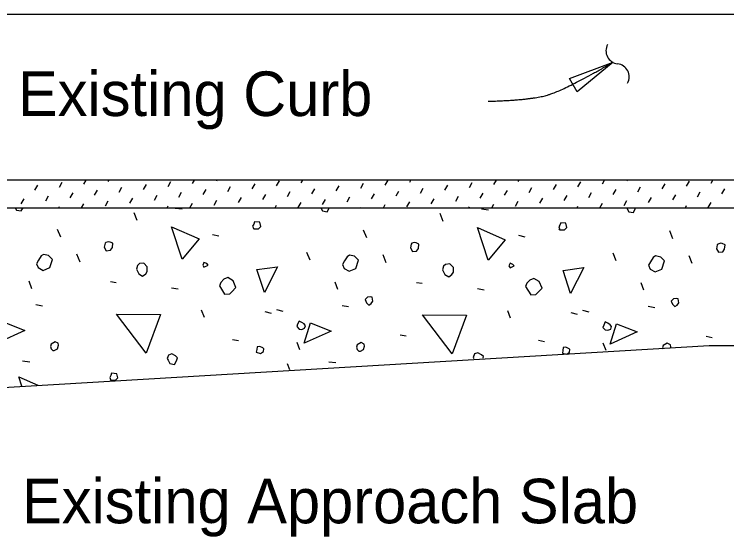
# Model space of a CAD drawing. Extents: x 21587 to 21656.3, y 56117.4 to 56157.3.
# Drawn here: x 21596.035 to 21599.259, y 56132.438 to 56134.801 of the extents above; entities that cross this region are included whole.
import ezdxf

# ---------------------------------------------------------------- set-up
doc = ezdxf.new("R2010")
doc.units = 0
for name, color, linetype in [('AdhocPoint_dp', 7, 'Continuous'), ('PlotBorder_dp', 7, 'Continuous'), ('SheetBorder_dp', 7, 'Continuous'), ('TextMisc', 7, 'Continuous')]:
    doc.layers.add(name, color=color, linetype=linetype)

msp = doc.modelspace()

# ---------------------------------------------------------------- linework, layer by layer
at = {"layer": 'AdhocPoint_dp'}
for p, q in [((21593.9596, 56134.8009), (21601.9067, 56134.8009)), ((21604.323, 56134.0511), (21593.9596, 56134.0511)), ((21593.9596, 56133.926), (21604.323, 56133.926)), ((21599.1795, 56133.301), (21594.9595, 56133.051)), ((21604.323, 56133.301), (21599.1795, 56133.301))]:
    msp.add_line(p, q, dxfattribs=at)
at = {"layer": 'PlotBorder_dp'}
msp.add_lwpolyline([(21598.7452, 56134.5845), (21598.5825, 56134.4497), (21598.5472, 56134.5108)], close=True, dxfattribs=at)
for centre, start, end in [((21598.7718, 56134.636), 151.5267, 263.2539), ((21598.7578, 56134.5176), 331.5267, 83.2539)]:
    msp.add_arc(centre, 0.0596, start, end, dxfattribs=at)
msp.add_open_spline([(21598.18, 56134.4075), (21598.3615, 56134.4123), (21598.5206, 56134.4547), (21598.7452, 56134.5845)], degree=2, dxfattribs=at)
at = {"layer": 'TextMisc'}
for p, q in [((21596.1289, 56134.0059), (21596.1418, 56134.0283)), ((21596.2395, 56134.0189), (21596.2525, 56134.0413)), ((21596.3501, 56134.0319), (21596.3613, 56134.0511)), ((21596.4608, 56134.0448), (21596.4644, 56134.0511)), ((21596.6202, 56134.009), (21596.6332, 56134.0314)), ((21596.7309, 56134.0219), (21596.7438, 56134.0443)), ((21596.8415, 56134.0349), (21596.8509, 56134.0511)), ((21596.9521, 56134.0479), (21596.954, 56134.0511)), ((21597.1116, 56134.012), (21597.1246, 56134.0344)), ((21597.2222, 56134.0249), (21597.2352, 56134.0473)), ((21597.3329, 56134.0379), (21597.3405, 56134.0511)), ((21597.4435, 56134.0509), (21597.4436, 56134.0511)), ((21597.4923, 56134.002), (21597.5053, 56134.0244)), ((21597.603, 56134.015), (21597.6159, 56134.0374)), ((21597.7136, 56134.028), (21597.7266, 56134.0504)), ((21597.8242, 56134.0409), (21597.8301, 56134.0511)), ((21597.9837, 56134.0051), (21597.9967, 56134.0275)), ((21598.0943, 56134.018), (21598.1073, 56134.0404)), ((21598.205, 56134.031), (21598.2166, 56134.0511)), ((21598.3156, 56134.044), (21598.3197, 56134.0511)), ((21598.4751, 56134.0081), (21598.488, 56134.0305)), ((21598.5857, 56134.021), (21598.5987, 56134.0434)), ((21598.6963, 56134.034), (21598.7062, 56134.0511)), ((21598.807, 56134.047), (21598.8094, 56134.0511)), ((21598.9664, 56134.0111), (21598.9794, 56134.0335)), ((21599.0771, 56134.0241), (21599.09, 56134.0465)), ((21599.1877, 56134.037), (21599.1958, 56134.0511)), ((21596.2883, 56133.9701), (21596.3013, 56133.9925)), ((21596.399, 56133.983), (21596.4119, 56134.0054)), ((21596.5096, 56133.996), (21596.5226, 56134.0184)), ((21596.7797, 56133.9731), (21596.7927, 56133.9955)), ((21596.8903, 56133.9861), (21596.9033, 56134.0084)), ((21597.001, 56133.999), (21597.0139, 56134.0214)), ((21597.2711, 56133.9761), (21597.284, 56133.9985)), ((21597.3817, 56133.9891), (21597.3947, 56134.0115)), ((21597.7624, 56133.9791), (21597.7754, 56134.0015)), ((21597.8731, 56133.9921), (21597.886, 56134.0145)), ((21598.2538, 56133.9822), (21598.2668, 56134.0045)), ((21598.3644, 56133.9951), (21598.3774, 56134.0175)), ((21598.6345, 56133.9722), (21598.6475, 56133.9946)), ((21598.7452, 56133.9852), (21598.7581, 56134.0076)), ((21598.8558, 56133.9981), (21598.8688, 56134.0205)), ((21599.1259, 56133.9752), (21599.1389, 56133.9976)), ((21599.2365, 56133.9882), (21599.2495, 56134.0106)), ((21596.0671, 56133.9441), (21596.08, 56133.9665)), ((21596.1777, 56133.9571), (21596.1907, 56133.9795)), ((21596.5584, 56133.9472), (21596.5714, 56133.9696)), ((21596.6691, 56133.9601), (21596.682, 56133.9825)), ((21597.0498, 56133.9502), (21597.0628, 56133.9726)), ((21597.1604, 56133.9631), (21597.1734, 56133.9855)), ((21597.4305, 56133.9402), (21597.4435, 56133.9626)), ((21597.5412, 56133.9532), (21597.5541, 56133.9756)), ((21597.6518, 56133.9662), (21597.6648, 56133.9886)), ((21597.9219, 56133.9433), (21597.9349, 56133.9657)), ((21598.0325, 56133.9562), (21598.0455, 56133.9786)), ((21598.1432, 56133.9692), (21598.1561, 56133.9916)), ((21598.4133, 56133.9463), (21598.4262, 56133.9687)), ((21598.5239, 56133.9592), (21598.5369, 56133.9816)), ((21598.9046, 56133.9493), (21598.9176, 56133.9717)), ((21599.0153, 56133.9623), (21599.0282, 56133.9847)), ((21596.2368, 56133.926), (21596.2395, 56133.9307)), ((21596.34, 56133.926), (21596.3501, 56133.9436)), ((21596.4478, 56133.9342), (21596.4608, 56133.9566)), ((21596.7264, 56133.926), (21596.7309, 56133.9337)), ((21596.8296, 56133.926), (21596.8415, 56133.9466)), ((21596.9392, 56133.9372), (21596.9521, 56133.9596)), ((21597.2161, 56133.926), (21597.2222, 56133.9367)), ((21597.3199, 56133.9273), (21597.3329, 56133.9497)), ((21597.7057, 56133.926), (21597.7136, 56133.9397)), ((21597.8113, 56133.9303), (21597.8242, 56133.9527)), ((21598.0922, 56133.926), (21598.0943, 56133.9298)), ((21598.1953, 56133.926), (21598.205, 56133.9427)), ((21598.3026, 56133.9333), (21598.3156, 56133.9557)), ((21598.5818, 56133.926), (21598.5857, 56133.9328)), ((21598.6849, 56133.926), (21598.6963, 56133.9458)), ((21598.794, 56133.9363), (21598.807, 56133.9587)), ((21599.0714, 56133.926), (21599.0771, 56133.9358)), ((21599.1747, 56133.9264), (21599.1877, 56133.9488)), ((21596.5913, 56133.8676), (21596.5771, 56133.903)), ((21596.7639, 56133.9236), (21596.7957, 56133.9201)), ((21597.6025, 56133.926), (21597.603, 56133.9268)), ((21597.9759, 56133.8641), (21597.9618, 56133.8995)), ((21598.1485, 56133.9201), (21598.1804, 56133.9165)), ((21596.2454, 56133.7928), (21596.2313, 56133.8281)), ((21596.9318, 56133.8051), (21596.9601, 56133.7981)), ((21597.6301, 56133.7892), (21597.6159, 56133.8246)), ((21598.3165, 56133.8016), (21598.3448, 56133.7945)), ((21599.0148, 56133.7857), (21599.0006, 56133.8211)), ((21596.3332, 56133.6803), (21596.319, 56133.7156)), ((21597.3737, 56133.6885), (21597.3596, 56133.7238)), ((21597.7178, 56133.6767), (21597.7037, 56133.7121)), ((21598.7584, 56133.6849), (21598.7443, 56133.7203)), ((21599.1025, 56133.6732), (21599.0884, 56133.7085)), ((21596.1146, 56133.5594), (21596.1022, 56133.593)), ((21596.471, 56133.5919), (21596.4958, 56133.5883)), ((21597.4993, 56133.5559), (21597.4869, 56133.5895)), ((21597.8557, 56133.5883), (21597.8805, 56133.5848)), ((21598.8839, 56133.5524), (21598.8716, 56133.5859)), ((21596.7468, 56133.5636), (21596.7769, 56133.5583)), ((21598.1315, 56133.5601), (21598.1615, 56133.5547)), ((21596.1334, 56133.4876), (21596.1635, 56133.4823)), ((21597.5181, 56133.484), (21597.5481, 56133.4787)), ((21598.9028, 56133.4805), (21598.9328, 56133.4752)), ((21596.8953, 56133.4292), (21596.8829, 56133.4628)), ((21597.1693, 56133.4558), (21597.1976, 56133.4487)), ((21597.2217, 56133.4657), (21597.25, 56133.4587)), ((21598.28, 56133.4257), (21598.2676, 56133.4593)), ((21598.554, 56133.4522), (21598.5823, 56133.4451)), ((21598.6064, 56133.4622), (21598.6347, 56133.4551)), ((21597.7815, 56133.3515), (21597.808, 56133.3462)), ((21597.0226, 56133.3302), (21597.0491, 56133.3249)), ((21597.3278, 56133.2831), (21597.3154, 56133.3167)), ((21598.4073, 56133.3267), (21598.4338, 56133.3214)), ((21599.1657, 56133.3444), (21599.1922, 56133.3391)), ((21598.7125, 56133.2796), (21598.7001, 56133.3132)), ((21596.0733, 56133.233), (21596.1051, 56133.2295)), ((21597.2818, 56133.1928), (21597.2712, 56133.2194)), ((21597.458, 56133.2295), (21597.4898, 56133.2259))]:
    msp.add_line(p, q, dxfattribs=at)
for points in [[(21596.0394, 56133.926), (21596.0456, 56133.9147), (21596.0669, 56133.9112), (21596.0751, 56133.926)], [(21597.4221, 56133.926), (21597.4303, 56133.9112), (21597.4515, 56133.9077), (21597.4604, 56133.9236), (21597.461, 56133.926)], [(21598.8049, 56133.926), (21598.8062, 56133.9236)], [(21598.8062, 56133.9236), (21598.815, 56133.9077), (21598.8362, 56133.9041), (21598.845, 56133.9201), (21598.8465, 56133.926)], [(21596.7945, 56133.6926), (21596.7468, 56133.8394), (21596.8723, 56133.7846), (21596.7945, 56133.6926)], [(21597.1192, 56133.8299), (21597.1404, 56133.8299), (21597.151, 56133.8405), (21597.1457, 56133.8599), (21597.1227, 56133.8617), (21597.1192, 56133.8511), (21597.1139, 56133.8423), (21597.1192, 56133.8299), (21597.1157, 56133.8334)], [(21598.1792, 56133.6891), (21598.1315, 56133.8358), (21598.257, 56133.781), (21598.1792, 56133.6891)], [(21598.5039, 56133.8264), (21598.5251, 56133.8264), (21598.5357, 56133.837), (21598.5304, 56133.8564), (21598.5074, 56133.8582), (21598.5039, 56133.8476), (21598.4986, 56133.8387), (21598.5039, 56133.8264), (21598.5003, 56133.8299)], [(21596.4428, 56133.7474), (21596.4516, 56133.7315), (21596.471, 56133.7333), (21596.4799, 56133.7457), (21596.4817, 56133.7651), (21596.4693, 56133.7704), (21596.4604, 56133.7722), (21596.4498, 56133.7686), (21596.4463, 56133.7651), (21596.4428, 56133.7474)], [(21597.8274, 56133.7439), (21597.8363, 56133.728), (21597.8557, 56133.7298), (21597.8646, 56133.7421), (21597.8663, 56133.7616), (21597.854, 56133.7669), (21597.8451, 56133.7686), (21597.8345, 56133.7651), (21597.831, 56133.7616), (21597.8274, 56133.7439)], [(21599.2121, 56133.7404), (21599.221, 56133.7245), (21599.2404, 56133.7262), (21599.2492, 56133.7386), (21599.251, 56133.758), (21599.2386, 56133.7633), (21599.2298, 56133.7651), (21599.2192, 56133.7616), (21599.2156, 56133.758), (21599.2121, 56133.7404)], [(21596.1429, 56133.6549), (21596.1658, 56133.6425), (21596.1959, 56133.6549), (21596.2083, 56133.692), (21596.1906, 56133.7097), (21596.1676, 56133.715), (21596.157, 56133.7079), (21596.1446, 56133.6885), (21596.1358, 56133.6726), (21596.1429, 56133.6549)], [(21597.5275, 56133.6514), (21597.5505, 56133.639), (21597.5806, 56133.6514), (21597.593, 56133.6885), (21597.5753, 56133.7062), (21597.5523, 56133.7115), (21597.5417, 56133.7044), (21597.5293, 56133.6849), (21597.5205, 56133.669), (21597.5275, 56133.6514)], [(21598.9122, 56133.6478), (21598.9352, 56133.6354), (21598.9653, 56133.6478), (21598.9776, 56133.6849), (21598.9599, 56133.7026), (21598.937, 56133.7079), (21598.9264, 56133.7008), (21598.914, 56133.6814), (21598.9051, 56133.6655), (21598.9122, 56133.6478)], [(21596.5877, 56133.6484), (21596.5983, 56133.6272), (21596.616, 56133.6166), (21596.6301, 56133.6272), (21596.6372, 56133.6378), (21596.6372, 56133.659), (21596.6213, 56133.675), (21596.6019, 56133.6732), (21596.593, 56133.6644), (21596.5877, 56133.6484)], [(21596.8935, 56133.6573), (21596.913, 56133.6661), (21596.9059, 56133.6732), (21596.8935, 56133.6785), (21596.8882, 56133.6661), (21596.8935, 56133.6573)], [(21597.9724, 56133.6449), (21597.983, 56133.6237), (21598.0007, 56133.6131), (21598.0148, 56133.6237), (21598.0219, 56133.6343), (21598.0219, 56133.6555), (21598.006, 56133.6714), (21597.9865, 56133.6697), (21597.9777, 56133.6608), (21597.9724, 56133.6449)], [(21598.2782, 56133.6537), (21598.2977, 56133.6626), (21598.2906, 56133.6697), (21598.2782, 56133.675), (21598.2729, 56133.6626), (21598.2782, 56133.6537)], [(21597.1669, 56133.5417), (21597.1333, 56133.646), (21597.227, 56133.6584), (21597.1669, 56133.5417)], [(21598.5516, 56133.5382), (21598.518, 56133.6425), (21598.6117, 56133.6549), (21598.5516, 56133.5382)], [(21596.9643, 56133.5724), (21596.9872, 56133.5353), (21597.0102, 56133.5371), (21597.0191, 56133.5459), (21597.0385, 56133.5654), (21597.0261, 56133.5954), (21597.0014, 56133.6096), (21596.9837, 56133.6025), (21596.9696, 56133.5883), (21596.9643, 56133.5724)], [(21598.3489, 56133.5689), (21598.3719, 56133.5318), (21598.3949, 56133.5335), (21598.4037, 56133.5424), (21598.4232, 56133.5618), (21598.4108, 56133.5919), (21598.3861, 56133.606), (21598.3684, 56133.5989), (21598.3542, 56133.5848), (21598.3489, 56133.5689)], [(21597.6294, 56133.4964), (21597.6401, 56133.4858), (21597.6507, 56133.4929), (21597.6577, 56133.5035), (21597.6542, 56133.5212), (21597.6454, 56133.5229), (21597.633, 56133.5212), (21597.6224, 56133.5106), (21597.6294, 56133.4964)], [(21599.0136, 56133.4893), (21599.0242, 56133.4787), (21599.0348, 56133.4858), (21599.0419, 56133.4964), (21599.0384, 56133.5141), (21599.0295, 56133.5159), (21599.0172, 56133.5141), (21599.0066, 56133.5035), (21599.0136, 56133.4893)], [(21596.6319, 56133.2684), (21596.4976, 56133.4451), (21596.6973, 56133.4434), (21596.6319, 56133.2684)], [(21597.3242, 56133.3773), (21597.3366, 56133.3756), (21597.349, 56133.3809), (21597.3525, 56133.3915), (21597.3472, 56133.4003), (21597.3366, 56133.4074), (21597.3242, 56133.4127), (21597.3172, 56133.3986), (21597.3136, 56133.388), (21597.3242, 56133.3773)], [(21598.0166, 56133.2648), (21597.8822, 56133.4416), (21598.082, 56133.4398), (21598.0166, 56133.2648)], [(21595.9619, 56133.3161), (21595.9902, 56133.408), (21596.0839, 56133.3709), (21595.9619, 56133.3161)], [(21597.3466, 56133.3126), (21597.3749, 56133.4045), (21597.4686, 56133.3674), (21597.3466, 56133.3126)], [(21598.7089, 56133.3738), (21598.7213, 56133.372), (21598.7337, 56133.3773), (21598.7372, 56133.388), (21598.7319, 56133.3968), (21598.7213, 56133.4039), (21598.7089, 56133.4092), (21598.7019, 56133.395), (21598.6983, 56133.3844), (21598.7089, 56133.3738)], [(21598.7313, 56133.309), (21598.7596, 56133.401), (21598.8533, 56133.3638), (21598.7313, 56133.309)], [(21596.2094, 56133.2807), (21596.2165, 56133.2807), (21596.2306, 56133.2878), (21596.2359, 56133.3037), (21596.2342, 56133.3126), (21596.22, 56133.3196), (21596.2023, 56133.309), (21596.1988, 56133.2984), (21596.2023, 56133.2878), (21596.2094, 56133.2807)], [(21597.5941, 56133.2772), (21597.6012, 56133.2772), (21597.6153, 56133.2843), (21597.6206, 56133.3002), (21597.6188, 56133.309), (21597.6047, 56133.3161), (21597.587, 56133.3055), (21597.5835, 56133.2949), (21597.587, 56133.2843), (21597.5941, 56133.2772)], [(21597.1304, 56133.2719), (21597.1499, 56133.2666), (21597.1622, 56133.2754), (21597.164, 56133.2878), (21597.1605, 56133.2914), (21597.1463, 56133.2984), (21597.134, 56133.2967), (21597.1322, 56133.2843), (21597.1304, 56133.2719)], [(21598.5151, 56133.2684), (21598.5345, 56133.2631), (21598.5469, 56133.2719), (21598.5487, 56133.2843), (21598.5452, 56133.2878), (21598.531, 56133.2949), (21598.5186, 56133.2931), (21598.5169, 56133.2807), (21598.5151, 56133.2684)], [(21599.003, 56133.2899), (21599.0053, 56133.2967), (21599.0035, 56133.3055), (21598.9894, 56133.3126), (21598.9717, 56133.302), (21598.9682, 56133.2914), (21598.9693, 56133.2878)], [(21596.7309, 56133.2366), (21596.7397, 56133.2206), (21596.761, 56133.2171), (21596.7698, 56133.233), (21596.7733, 56133.2472), (21596.7645, 56133.256), (21596.7486, 56133.2648), (21596.7327, 56133.2595), (21596.7274, 56133.2436), (21596.7309, 56133.2366)], [(21598.1564, 56133.2458), (21598.158, 56133.2524), (21598.1492, 56133.2612), (21598.1333, 56133.2701), (21598.1174, 56133.2648), (21598.112, 56133.2489), (21598.1149, 56133.2432)], [(21596.07, 56133.1187), (21596.0562, 56133.1609), (21596.1425, 56133.1233)], [(21596.4724, 56133.1452), (21596.4936, 56133.1452), (21596.5042, 56133.1558), (21596.4989, 56133.1752), (21596.4759, 56133.177), (21596.4724, 56133.1664), (21596.4671, 56133.1575), (21596.4724, 56133.1452), (21596.4689, 56133.1487)]]:
    msp.add_lwpolyline(points, dxfattribs=at)

# ---------------------------------------------------------------- texts
at = {"layer": 'SheetBorder_dp'}
for s, p in [('Existing Curb', (21596.0521, 56134.3406)), ('Existing Approach Slab', (21596.0704, 56132.4985))]:
    msp.add_text(s, height=0.2016, dxfattribs=at).set_placement(p)

doc.saveas('drawing.dxf')
